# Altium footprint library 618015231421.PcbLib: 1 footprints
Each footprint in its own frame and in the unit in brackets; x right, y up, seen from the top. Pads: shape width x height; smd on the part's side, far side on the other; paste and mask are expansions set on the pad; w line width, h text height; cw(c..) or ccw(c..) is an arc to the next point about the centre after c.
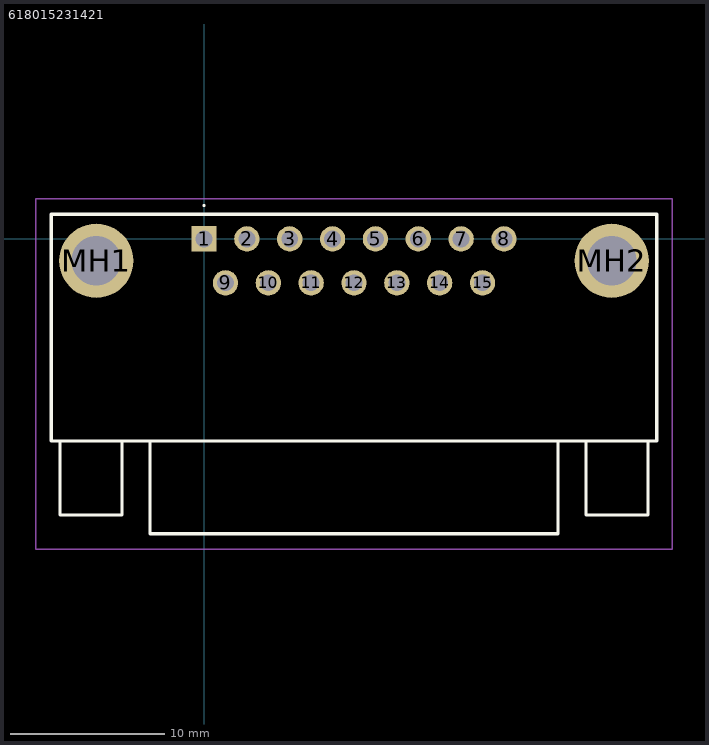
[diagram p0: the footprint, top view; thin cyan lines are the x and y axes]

## 618015231421 [mm]
pads (17):
  rect 1.635x1.635 hole 1.09: 1(0,0)
  round 1.635 hole 1.09: 2(2.77,0) 3(5.54,0) 4(8.31,0) 5(11.08,0) 6(13.85,0) 7(16.62,0) 8(19.39,0) 9(1.385,-2.84) 10(4.155,-2.84) 11(6.925,-2.84) 12(9.695,-2.84) 13(12.465,-2.84) 14(15.235,-2.84) 15(18.005,-2.84)
  round 4.8 hole 3.2: MH1(-6.965,-1.42) MH2(26.355,-1.42)
Top Overlay:
  lines w0.1: 0,2.1 cw(c0,2.15) 0,2.2 ; 0,2.1 0,2.1 ; 0,2.1 ccw(c0,2.15) 0,2.2 ; 0,2.2 0,2.2
  lines w0.2: -9.305,-13.06 -9.305,-17.86 -5.305,-17.86 -5.305,-13.06 ; -3.495,-13.06 -3.495,-19.06 22.885,-19.06 22.885,-13.06 ; 24.695,-13.06 24.695,-17.86 28.695,-17.86 28.695,-13.06 ; -9.875,-13.06 29.265,-13.06 29.265,1.59 -9.875,1.59 -9.875,-13.06
Mechanical 15:
  lines w0.1: -9.305,-13.06 -9.305,-17.86 -5.305,-17.86 -5.305,-13.06 ; -3.495,-13.06 -3.495,-19.06 22.885,-19.06 22.885,-13.06 ; 24.695,-13.06 24.695,-17.86 28.695,-17.86 28.695,-13.06 ; -9.875,-13.06 29.265,-13.06 29.265,1.59 -9.875,1.59 -9.875,-13.06
Mechanical 20:
  lines w0.1: -10.875,-20.06 30.265,-20.06 30.265,2.59 -10.875,2.59 -10.875,-20.06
